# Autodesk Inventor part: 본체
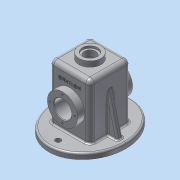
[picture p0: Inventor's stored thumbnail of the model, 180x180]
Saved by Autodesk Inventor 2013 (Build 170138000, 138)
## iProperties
Created: 2017-07
Part Number: 본체
Material: 알루미늄 6061
Document SubType Name: Modeling
Designer: dgall
Density: 2.71 g/cm^3
Mass: 894.433 g
Surface Area: 989.929 cm^2
Volume: 330.049 cm^3
Author: dgall
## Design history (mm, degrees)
sketch "스케치1"
  geometry: L1 (-37, -37)-(37, -37); L2 (37, -37)-(37, 37); L3 (37, 37)-(-37, 37); L4 (-37, 37)-(-37, -37); L5 (-37, -37)-(37, 37); L6 (37, -37)-(-37, 37); 1 further point
  constraints: 12 end point, 2 midpoint, 2 parallel, 1 horizontal, 1 perpendicular
  dimensions: "d12" = 74 distance of L3.end L2.end; "d13" = 74 distance of L2.end L1.end
extrude "돌출1" new body sketch "스케치1" distance "d2" = 110; taper "d3" = 0 deg
feature "쉘1" dims "d4" = 5
sketch "스케치2"
  geometry: L1 (-50, 55)-(-25, 55); L2 (-25, 55)-(-25, 75.5); L3 (-25, 75.5)-(-32, 82.5); L4 (-37, 82.5)-(-50, 82.5); L5 (-50, 82.5)-(-50, 55); L6 (-37, 82.5)-(-32, 82.5); L7 (32, 0)-(-32, 0) reference; L8 (-37, 0)-(-37, 110) reference; L9 (-32, 0)-(-32, 105) reference
  constraints: 12 end point, 3 perpendicular, 2 point on line
  dimensions: "d6" = 55 diameter of L4 L1; "d7" = 13 distance of L4.start L4.end; "d8" = 7 horizontal distance of L2.end L3.end; "d9" = 55 diameter of L3.end L1; "d14" = 55 distance between parallel lines of L7 L1; "d15" = 135 deg angle of L9 L3
revolve "회전1" sketch "스케치2" stored, may be unused: angle "d11" = 90 deg
hole "구멍1" diameter "d18" = 32; stored, may be unused: countersink angle "d22" = 90 deg, drill point angle "d24" = 118 deg; dims "d16" = 10, "d17" = 10, "d19" = 6, "d20" = 4, "d21" = 2, "d23" = 8
fillet "모깎기1" dims "d25" = 8
fillet "모깎기2" dims "d26" = 8
fillet "모깎기3" dims "d27" = 3
fillet "모깎기4" dims "d28" = 3
node "작업 평면1"
sketch "스케치3"
  geometry: L1 (20, -20)-(-20, -20); L2 (-20, -20)-(-20, 20); L3 (-20, 20)-(20, 20); L4 (20, 20)-(20, -20); L5 (20, -20)-(-20, 20); L6 (-20, -20)-(20, 20); C1 r 14 at (0, 0); C2 r 20 at (0, 0); C3 r 10.5 at (0, 0); 1 further point
  constraints: 12 end point, 3 centre point, 3 coincident, 2 midpoint, 2 parallel, 1 horizontal, 1 perpendicular
  dimensions: "d30" = 28 diameter of C1; "d31" = 40 diameter of C2; "d32" = 21 diameter of C3; "d72" = 40 distance of L2.end L3.end; "d73" = 40 distance of L1.end L2.end
extrude "돌출2" join sketch "스케치3" stored distance "d33" = 110; taper "d34" = 0 deg
hole "구멍2" diameter "d41" = 21; stored, may be unused: countersink angle "d45" = 90 deg, drill point angle "d47" = 118 deg; dims "d39" = 10, "d40" = 10, "d42" = 6, "d43" = 28, "d44" = 4, "d46" = 8
sketch "스케치4"
  geometry: L1 (-37, -29)-(-37, 29) reference; L2 (29, -37)-(-29, -37) reference; L3 (37, 29)-(37, -29) reference; L4 (-29, 37)-(29, 37) reference; L5 (0, -75)-(0, 75); L6 (0, 0)-(-65, 0); L7 (0, 0)-(65, 0); A1 r 8 centre (-29, 29) between (-29, 37) and (-37, 29) reference; A2 r 8 centre (-29, -29) between (-37, -29) and (-29, -37) reference; A3 r 8 centre (29, -29) between (29, -37) and (37, -29) reference; A4 r 8 centre (29, 29) between (37, 29) and (29, 37) reference; 2 further points; 1 other entity
  constraints: 6 end point, 2 coincident, 2 perpendicular, 1 midpoint, 1 symmetric about line, 1 vertical, 4 other
  dimensions: "d48" = 150 distance of L5.start L5.end; "d49" = 65 distance of L6.start L6.end
extrude "돌출5" join sketch "스케치4" distance "d50" = 10; taper "d51" = 0 deg
sketch "스케치5"
  geometry: 3 further points; 1 other entity
  constraints: 2 vertical alignment, 1 other
  dimensions: "d52" = 58 distance of point (0, 0) point (0, 58); "d53" = 58 distance of point (0, -58) point (0, 0)
hole "구멍3" sketch "스케치5" at (0, 58), (0, -58) diameter "d54" = 10; stored, may be unused: countersink angle "d58" = 90 deg, drill point angle "d60" = 118 deg; dims "d55" = 6, "d56" = 28, "d57" = 4, "d59" = 8
sketch "스케치6"
  geometry: L1 (-37, 10)-(-37, 102) reference; L2 (65, 10)-(-65, 10) reference; L3 (-55, 10)-(-37, 82.194); L4 (65, 10)-(-65, 10) reference; L5 (65, 0)-(-65, 0) reference; L6 (-37, 82.194)-(-35.802, 87); L7 (-35.802, 87)-(-35.802, 10); L8 (-55, 10)-(-35.802, 10); 1 further point
  constraints: 8 end point, 3 point on line, 2 perpendicular, 1 collinear
  dimensions: "d61" = 10 distance of L3.start L2.end; "d62" = 14 deg angle of L1 L3; "d63" = 77 distance of L6.end L7.end
extrude "돌출6" join sketch "스케치6" stored distance "d64" = 10; taper "d65" = 0 deg
fillet "모깎기6" dims "d67" = 3
fillet "모깎기7" dims "d68" = 3
fillet "모깎기8" dims "d69" = 3
fillet "모깎기9" dims "d70" = 3
fillet "모깎기10" dims "d71" = 3
sketch "스케치7"
  geometry: C1 r 16 at (0, 0) reference; 2 further points
  constraints: 1 vertical alignment
  dimensions: "d78" = 22.5 distance of point (0, 22.5) C1.centre
hole "구멍4" sketch "스케치7" at (0, 22.5) diameter "d79" = 3.459; stored, may be unused: countersink angle "d83" = 90 deg, drill point angle "d85" = 118 deg; dims "d80" = 8, "d81" = 28, "d82" = 4, "d84" = 10
chamfer "모따기1" distance "d89" = 1; stored, may be unused: second distance "d90" = 2, angle "d91" = 45 deg
fillet "모깎기13" dims "d92" = 0.5
sketch "스케치8"
  geometry: L1 (46, 18)-(12, 18) reference; L2 (66, -89)-(66, 0) reference; 2 further points
  constraints: 1 other
  dimensions: "d93" = 37 distance from line of point (29, -12) L2; "d94" = 30 distance from line of point (29, -12) L1
feature "엠보싱1" sketch "스케치8" dims "d95" = 0.5, "d96" = 0
node "솔리드1"
mirror "대칭1"
mirror "대칭2"
pattern_circular "원형 패턴1" dims angle "d87" = 360 deg
mirror "대칭3"
node "투영된 루프1"
